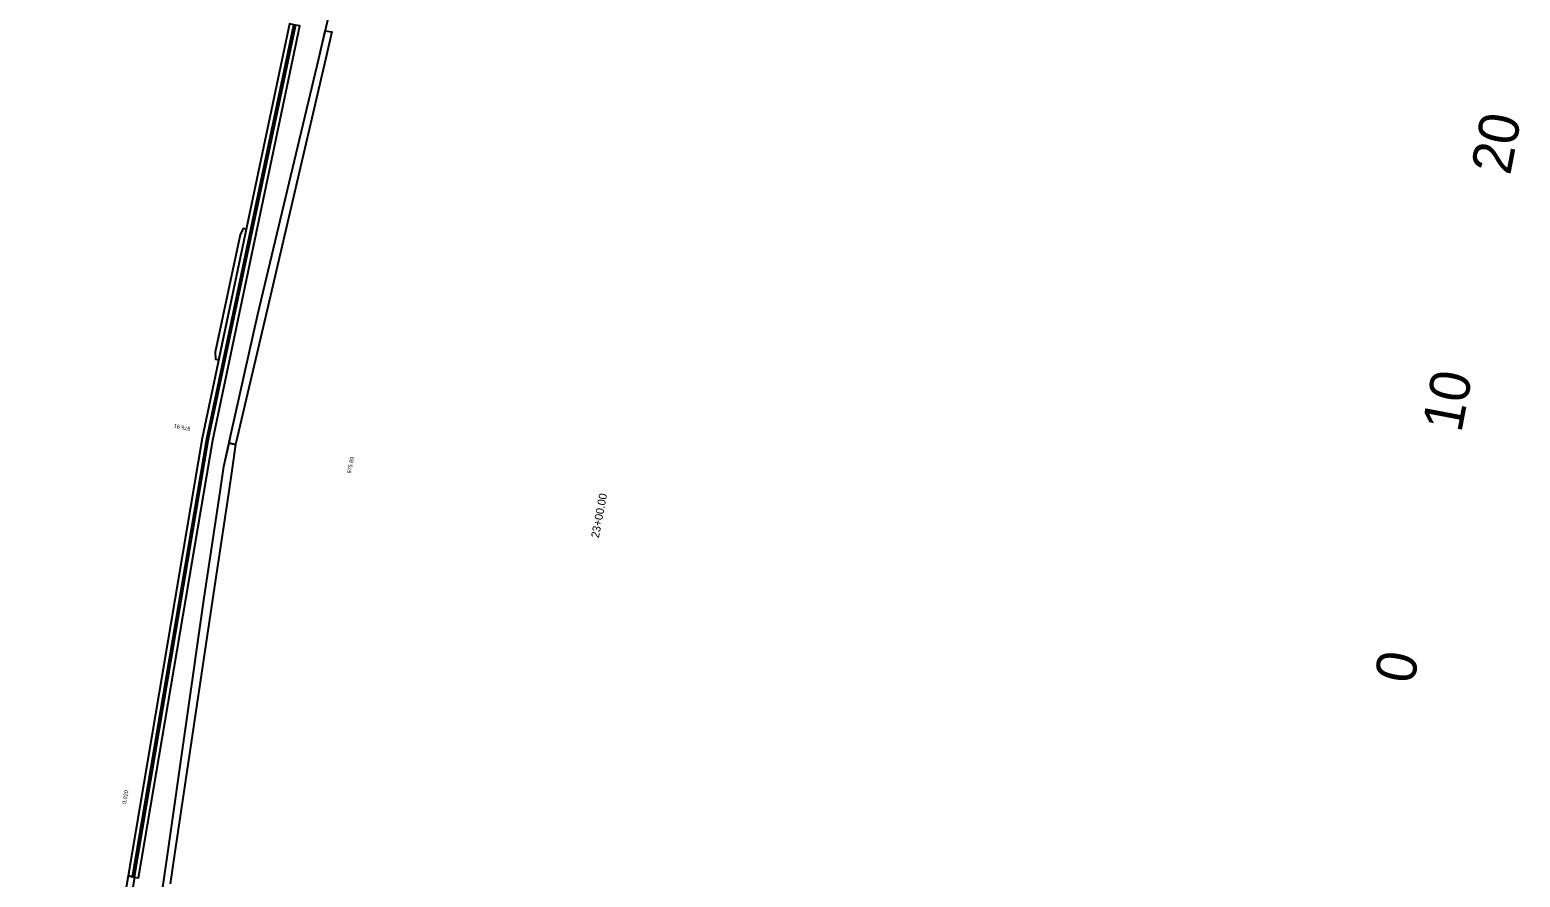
# Model space of a CAD drawing. Extents: x 1615680 to 1617075, y 898420 to 901168.
# Drawn here: x 1616094.5 to 1616150.3, y 898561.5 to 898593.2 of the extents above; entities that cross this region are included whole.
import ezdxf

# ---------------------------------------------------------------- set-up
doc = ezdxf.new("R2010")
doc.units = 0
for name, color, linetype in [('Exist XS Ground Line', 7, 'Continuous'), ('Prop CMT Pvmt Course 1', 7, 'Continuous'), ('Prop CMT Pvmt Course 2', 7, 'Continuous'), ('Prop CMT Pvmt Course 3', 7, 'Continuous'), ('Prop Conc Island Cover', 7, 'Continuous'), ('Prop Corridor Mesh Bottom', 7, 'Continuous'), ('Prop XS Alignment Label', 7, 'Continuous'), ('Prop XS Elevation Labels', 7, 'Continuous'), ('Prop XS Label Text', 7, 'Continuous'), ('Prop XS Offset Labels', 7, 'Continuous'), ('Prop XS SS Elevation Text', 7, 'Continuous'), ('Prop XS Station Labels', 7, 'Continuous'), ('Scratch_Level_9', 7, 'Continuous')]:
    doc.layers.add(name, color=color, linetype=linetype)

msp = doc.modelspace()

# ---------------------------------------------------------------- linework, layer by layer
at = {"layer": 'Exist XS Ground Line'}
msp.add_lwpolyline([(1616094.474, 898532.81), (1616097.577, 898546.747), (1616098.842, 898550.555), (1616099.242, 898552.106), (1616099.257, 898553.612), (1616099.351, 898560.316), (1616099.649, 898562.388), (1616101.01, 898571.938), (1616101.605, 898575.913), (1616101.75, 898576.86), (1616102.001, 898578), (1616103.016, 898582.572), (1616105.301, 898592.154), (1616105.819, 898594.343), (1616106.41, 898595.817), (1616109.32, 898605.354), (1616109.336, 898605.383), (1616112.341, 898609.773), (1616122.814, 898647.513)], dxfattribs=at)
at = {"layer": 'Prop CMT Pvmt Course 1'}
for points in [[(1616098.163, 898561.519), (1616098.326, 898561.488), (1616098.326, 898561.488), (1616101.103, 898577.895), (1616101.103, 898577.895), (1616104.372, 898593.412), (1616104.208, 898593.443), (1616104.208, 898593.443), (1616100.939, 898577.926), (1616100.939, 898577.926), (1616098.163, 898561.519), (1616098.163, 898561.519), (1616098.163, 898561.519)], [(1616098.163, 898561.519), (1616096.838, 898553.688), (1616096.838, 898553.688), (1616097.083, 898553.641), (1616098.408, 898561.472), (1616098.408, 898561.472), (1616098.163, 898561.519), (1616098.163, 898561.519), (1616098.163, 898561.519)]]:
    msp.add_lwpolyline(points, dxfattribs=at)
at = {"layer": 'Prop CMT Pvmt Course 2'}
msp.add_lwpolyline([(1616098.326, 898561.488), (1616098.388, 898561.476), (1616098.388, 898561.476), (1616101.164, 898577.884), (1616101.164, 898577.884), (1616104.433, 898593.401), (1616104.372, 898593.412), (1616104.372, 898593.412), (1616101.103, 898577.895), (1616101.103, 898577.895), (1616098.326, 898561.488), (1616098.326, 898561.488), (1616098.326, 898561.488)], dxfattribs=at)
at = {"layer": 'Prop CMT Pvmt Course 3'}
msp.add_lwpolyline([(1616098.388, 898561.476), (1616098.552, 898561.445), (1616098.552, 898561.445), (1616101.328, 898577.853), (1616101.328, 898577.853), (1616104.597, 898593.37), (1616104.433, 898593.401), (1616104.433, 898593.401), (1616101.164, 898577.884), (1616101.164, 898577.884), (1616098.388, 898561.476), (1616098.388, 898561.476), (1616098.388, 898561.476)], dxfattribs=at)
at = {"layer": 'Prop Conc Island Cover'}
msp.add_lwpolyline([(1616101.435, 898580.886), (1616101.558, 898580.863), (1616101.558, 898580.863), (1616102.589, 898585.756), (1616102.466, 898585.78), (1616102.466, 898585.78), (1616102.358, 898585.546), (1616102.358, 898585.546), (1616101.42, 898581.147), (1616101.42, 898581.147), (1616101.42, 898581.147), (1616101.435, 898580.886), (1616101.435, 898580.886)], dxfattribs=at)
at = {"layer": 'Prop Corridor Mesh Bottom'}
for points in [[(1616105.301, 898592.154), (1616105.546, 898593.189), (1616105.546, 898593.189), (1616105.792, 898593.143), (1616105.55, 898592.107), (1616105.55, 898592.107), (1616103.314, 898582.516), (1616103.314, 898582.516), (1616103.314, 898582.516), (1616102.25, 898577.953), (1616102.25, 898577.953), (1616102.189, 898577.689), (1616101.943, 898577.736), (1616101.943, 898577.736), (1616102.001, 898578), (1616102.001, 898578), (1616103.016, 898582.572), (1616103.016, 898582.572), (1616103.016, 898582.572), (1616105.301, 898592.154), (1616105.301, 898592.154)], [(1616101.75, 898576.86), (1616101.943, 898577.736), (1616101.943, 898577.736), (1616102.189, 898577.689), (1616102.056, 898576.802), (1616102.056, 898576.802), (1616101.915, 898575.854), (1616101.915, 898575.854), (1616101.323, 898571.879), (1616101.323, 898571.879), (1616101.323, 898571.879), (1616099.901, 898562.341), (1616099.901, 898562.341), (1616099.734, 898561.221)], [(1616099.488, 898561.267), (1616099.649, 898562.388), (1616099.649, 898562.388), (1616101.01, 898571.938), (1616101.01, 898571.938), (1616101.01, 898571.938), (1616101.605, 898575.913), (1616101.605, 898575.913), (1616101.75, 898576.86), (1616101.75, 898576.86)]]:
    msp.add_lwpolyline(points, dxfattribs=at)

# ---------------------------------------------------------------- texts
at = {"layer": 'Prop XS Alignment Label'}
msp.add_text('.', height=0.01, rotation=79.2494, dxfattribs=at).set_placement((1616141.844, 898570.432))
at = {"layer": 'Prop XS Elevation Labels'}
msp.add_text('976.91', height=0.15, rotation=169.2494, dxfattribs=at).set_placement((1616100.509, 898578.339))
at = {"layer": 'Prop XS Label Text'}
msp.add_text('0.020', height=0.15, rotation=80.3951, dxfattribs=at).set_placement((1616098.083, 898564.208))
at = {"layer": 'Prop XS Offset Labels'}
for s, p in [('20', (1616149.953, 898587.741)), ('10', (1616148.121, 898578.093)), ('0', (1616146.333, 898568.675)), ('0', (1616146.333, 898568.675))]:
    msp.add_text(s, height=1.5, rotation=79.2494, dxfattribs=at).set_placement(p)
at = {"layer": 'Prop XS SS Elevation Text'}
msp.add_text('975.89', height=0.15, rotation=79.2494, dxfattribs=at).set_placement((1616106.509, 898576.589))
at = {"layer": 'Prop XS Station Labels'}
msp.add_text('23+00.00', height=0.3, rotation=79.2494, dxfattribs=at).set_placement((1616115.799, 898574.168))
at = {"layer": 'Scratch_Level_9'}
msp.add_text('X', height=0.00025, rotation=79.2494, dxfattribs=at).set_placement((1616100.939, 898577.926))

doc.saveas('drawing.dxf')
